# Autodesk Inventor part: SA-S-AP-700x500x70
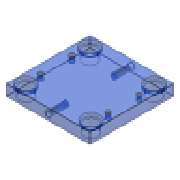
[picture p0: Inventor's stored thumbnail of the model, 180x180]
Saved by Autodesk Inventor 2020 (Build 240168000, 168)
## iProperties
Created: 2019-01
Part Number: SA-S-AP-700x500x70
Material: S 55 C
Description: Cavity Plate
Document SubType Name: Modeling
Designer: LENOVO-CADCIM
Standard Revision: 1
Manufacturer: FUTABA
Language: en-US
Size Designation: 700x500x70
Categories: <MemberInstance><Categories><Category DisplayName="Mold" InternalName="349578f2-f4d4-4954-8c09-8e99297a61c0" Mnemonic="MOLD"><Category DisplayName="Mold Plates"
Density: 7.85 g/cm^3
Appearance: Clear - Blue
IsCustomPart: 1
Author: LENOVO-CADCIM
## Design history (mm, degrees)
sketch "Sketch1"
  geometry: L1 (-250, 350)-(250, 350); L2 (250, 350)-(250, -350); L3 (250, -350)-(-250, -350); L4 (-250, -350)-(-250, 350); 3 further points
  constraints: 8 end point, 2 midpoint, 2 parallel, 1 horizontal, 1 horizontal alignment, 1 perpendicular, 1 vertical alignment
  dimensions: "d123" = 500 distance between parallel lines of L2 L4 (= W_); "d124" = 700 distance between parallel lines of L3 L1 (= L)
extrude "Extrusion1" new body sketch "Sketch1" distance "d20" = 70 (= H_); taper "d30" = 0 deg
sketch "Sketch2"
  geometry: 4 further points
  constraints: 1 horizontal alignment
  dimensions: "d125" = 205 horizontal distance of point (0, 0) point (-205, 243) (= 0.5 x S1_W); "d126" = 243 vertical distance of point (0, 0) point (-205, 243) (= 0.5 x S1_L); "d127" = 207 horizontal distance of point (0, 0) point (-207, 307) (= 0.5 x GB_W); "d128" = 307 vertical distance of point (0, 0) point (-207, 307) (= 0.5 x GB_L); "d129" = 207 horizontal distance of point (0, 0) point (207, 307) (= 0.5 x GB_W)
feature "Sculpt1"
feature "Sculpt3"
thread "Thread2" dims "d193" = 0, "d194" = 0
feature "Sculpt6"
body "Solid1"
sketch "Sketch3"
  geometry: L1 (500, 0)-(0, 0) reference; 3 further points
  constraints: 1 midpoint, 1 vertical alignment
  dimensions: "d169" = 35 distance from line of L1 point (250, 35) (= 0.5 x H_)
hole "Hole1" sketch "Sketch3" diameter "d170" = 31.67; stored, may be unused: countersink angle "d174" = 90 deg, drill point angle "d176" = 118 deg; dims "d171" = 59 (= le), "d172" = 4, "d173" = 2, "d175" = 82 (= ke)
sketch "Sketch4"
  geometry: L1 (0, 0)-(500, 0) reference; 4 further points
  constraints: 2 midpoint, 2 vertical alignment
  dimensions: "d177" = 35 distance from line of L1 point (250, -35) (= 0.5 x H_)
hole "Hole2" sketch "Sketch4" diameter "d178" = 31.67; stored, may be unused: countersink angle "d182" = 90 deg, drill point angle "d184" = 118 deg; dims "d179" = 59 (= le), "d180" = 4, "d181" = 2, "d183" = 82 (= ke)
hole "Hole3" sketch "Sketch2" diameter "d130" = 55 (= GB_d1); stored, may be unused: countersink angle "d134" = 90 deg, drill point angle "d136" = 0 deg; dims "d131" = 6, "d132" = 62 (= GB_d2), "d133" = 10 (= GB_k), "d135" = 70 (= H_)
pattern_linear "Rectangular Pattern1" dims "d159" = 614 (computed from GB_L, Nl)
hole "Hole4" sketch "Sketch2" diameter "d137" = 55 (= GB_d1); stored, may be unused: countersink angle "d141" = 90 deg, drill point angle "d143" = 0 deg; dims "d138" = 6, "d139" = 62 (= GB_d2), "d140" = 10 (= GB_k), "d142" = 70 (= H_)
pattern_linear "Rectangular Pattern2" dims "d162" = 612 (computed from GB_L2, GB_L1, Nl)
hole "Hole5" sketch "Sketch2" diameter "d144" = 13.835; stored, may be unused: countersink angle "d148" = 90 deg, drill point angle "d150" = 118 deg; dims "d145" = 20 (= H_l), "d146" = 62 (= GB_d2), "d147" = 10 (= GB_k), "d149" = 30 (= H_u)
pattern_linear "Rectangular Pattern3" dims "d153" = 243 (computed from S1_L, Ns), "d156" = 410 (computed from S1_W, Nw)
chamfer "Chamfer1" distance "d185" = 0.5; stored, may be unused: second distance "d186" = 2, angle "d187" = 45 deg
feature "Surface1"
body "Srf1"
feature "Surface3"
body "Srf3"
feature "Surface6"
body "Srf6"
other parameters: "L" = 700 [user parameter; used in 1 equation term], "W_" = 500 [user parameter; used in 1 equation term], "H_" = 70 [user parameter; used in 5 equation terms], "GB_W" = 414 [user parameter; used in 2 equation terms], "GB_d1" = 55 [user parameter; used in 2 equation terms], "GB_d2" = 62 [user parameter; used in 3 equation terms], "GB_k" = 10 [user parameter; used in 3 equation terms], "S1_L" = 486 [user parameter; used in 2 equation terms], "GB_L1" = 307 [user parameter; used in 1 equation term], "GB_L2" = 305 [user parameter; used in 1 equation term], "GB_L" = 614 [user parameter; used in 2 equation terms], "le" = 59 [user parameter; used in 2 equation terms], "ke" = 82 [user parameter; used in 2 equation terms], "H_l" = 20 [user parameter; used in 1 equation term], "H_u" = 30 [user parameter; used in 1 equation term]
